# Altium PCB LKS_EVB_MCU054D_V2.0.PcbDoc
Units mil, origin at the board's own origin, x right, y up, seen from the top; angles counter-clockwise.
Board outline 2625 x 1560 mil, 2 copper layers (Top Layer, Bottom Layer); 33 components, 57 nets, 169 pads, 53 vias.
Unrouted connection lines stored in the file: 24.
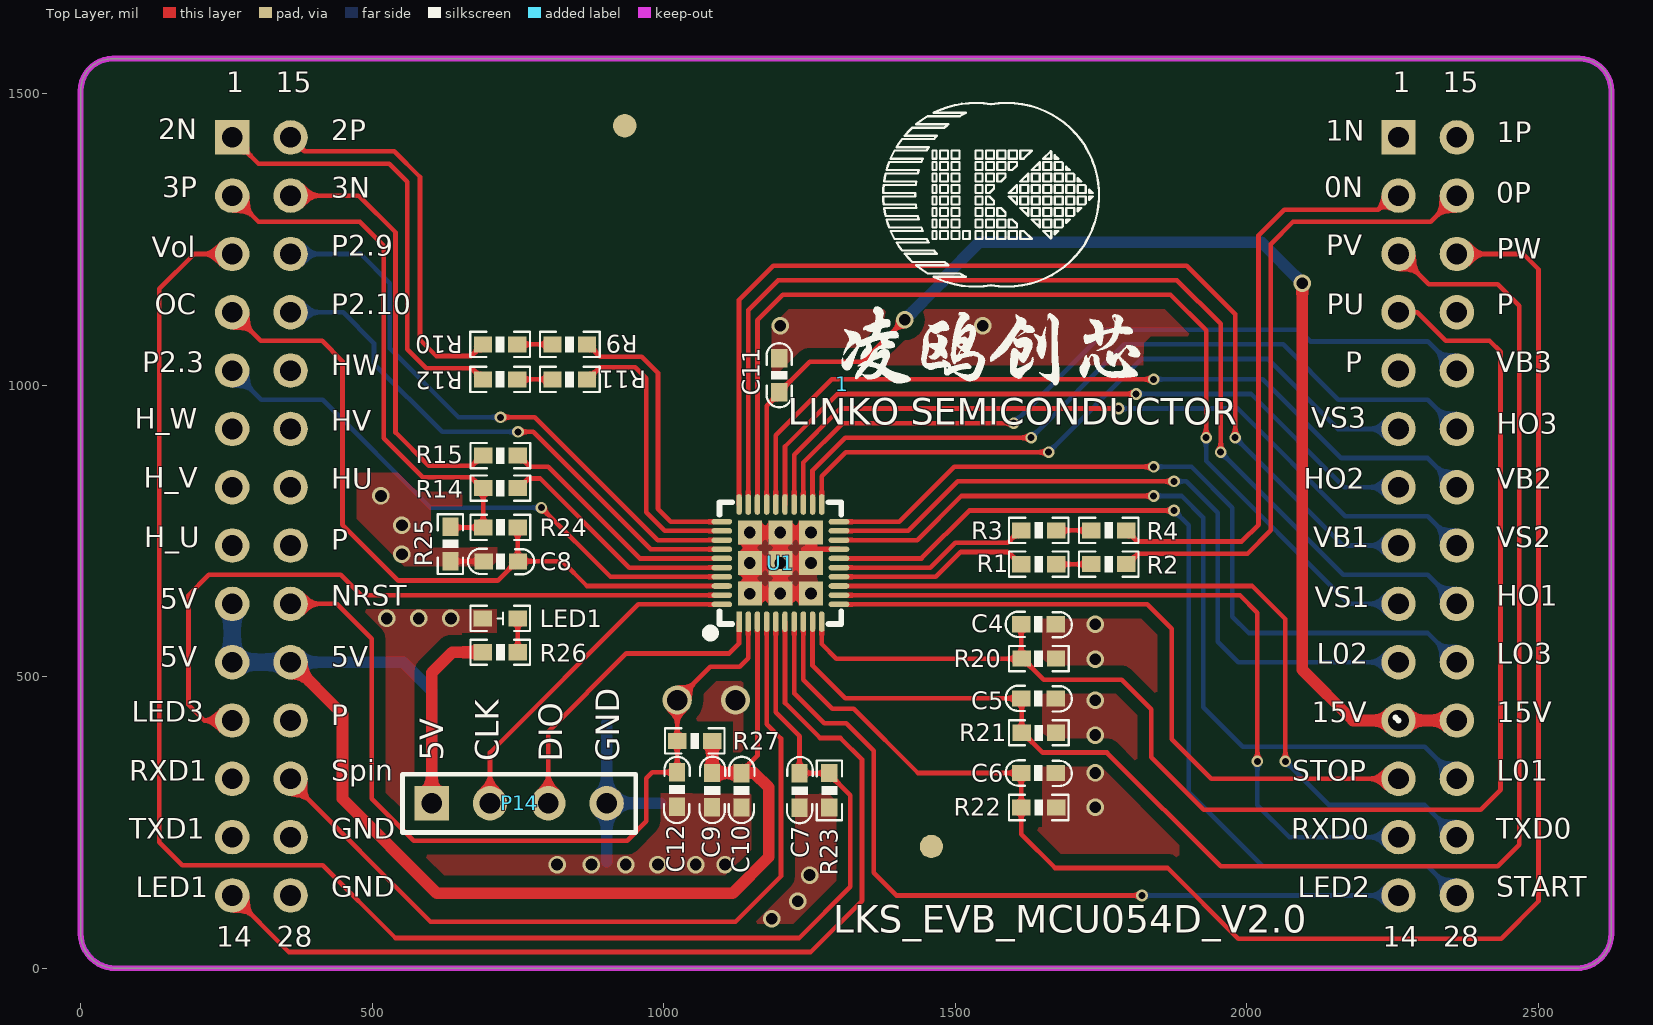
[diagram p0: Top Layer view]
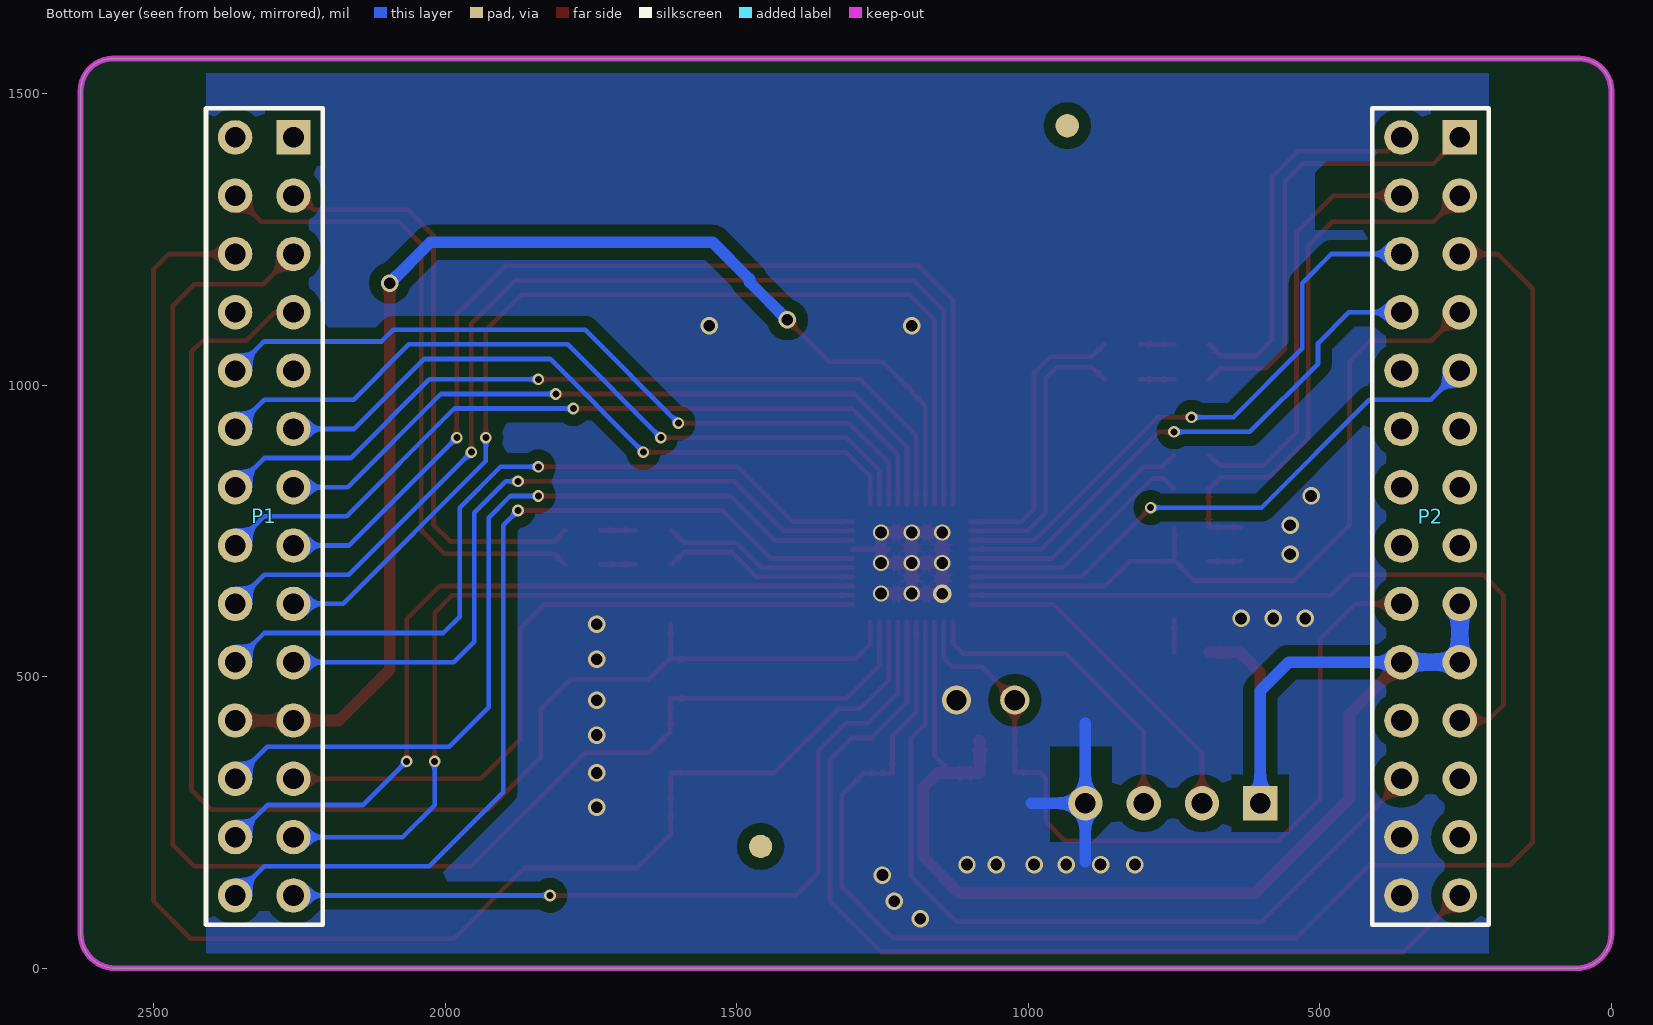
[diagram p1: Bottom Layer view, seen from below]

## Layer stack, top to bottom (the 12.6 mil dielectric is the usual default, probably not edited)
Top Solder: solder mask 0.4, Solder Resist, Dk 3.5
Top Layer: signal copper 1.4
Dielectric1: dielectric 12.6, FR-4, Dk 4.8
Bottom Layer: signal copper 1.4
Bottom Solder: solder mask 0.4, Solder Resist, Dk 3.5

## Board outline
0,60 ccw(c60,60) 60,0 2565,0 ccw(c2565,60) 2625,60 2625,1505 ccw(c2570,1505) 2570,1560 55,1560 ccw(c55,1505) 0,1505

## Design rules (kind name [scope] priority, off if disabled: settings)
Clearance Clearance_1 [InPolygon] p1: gap=20 ignorepadtopadclearanceinfootprint=FALSE except(0: Arc-Hole Track-Hole SMDPad-Hole THPad-Hole Via-Hole Fill-Hole Poly-Hole Region-Hole Text-Hole)
Clearance [All] p2 off: gap=10 ignorepadtopadclearanceinfootprint=FALSE except(0: Arc-Hole Track-Hole SMDPad-Hole THPad-Hole Via-Hole Fill-Hole Poly-Hole Region-Hole Text-Hole)
ComponentClearance [All] p1: gap=0 collisioncheckmode=3 verticalgap=0 showdistances=FALSE
FabricationTestpoint [(IsPad And (OnTopLayer Or OnBottomLayer))] p1: side=3 testpointundercomponent=TRUE minsize=40 maxsize=100 preferedsize=60 minholesize=0 maxholesize=40 preferedholesize=32 testpointgrid=1 allowsidetop=TRUE allowsidebottom=TRUE usegrid=TRUE gridtolerance=0.01
HoleSize [All] p1: absolutevalues=TRUE maxlimit=100 minlimit=0 maxpercent=80.000 minpercent=20.000
PolygonConnect [All] p1: connectstyle=Direct reliefconductorwidth=30 reliefentries=4 polygonreliefangle="90 Angle" airgapwidth=10
RoutingVias [All] p1: holewidth=28 width=50 viastyle="Through Hole" minholewidth=0 minwidth=10 maxholewidth=28 maxwidth=100
SilkToSolderMaskClearance SilkscreenOverComponentPads [IsPad] p1: minsilkscreentomaskgap=10 clearancetoexposedcopper=TRUE
SolderMaskExpansion [All] p1: expansion=4 istentingtop=FALSE
Width [All] p1: maxlimit=100 minlimit=2 preferedwidth=10
26 further rules are at their usual default settings.

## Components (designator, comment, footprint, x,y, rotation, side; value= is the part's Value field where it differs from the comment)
1 "LKS_sign" LKS_LOGO2 1306,1002 r0 top
C4 "1nF/16V" 0603C#1 1612.94,590 r0 top
C5 "1nF/16V" 0603C#1 1612.94,463 r0 top
C6 "1nF/16V" 0603C#1 1612.94,335 r0 top
C7 "100nF/50V" 0603C#1 1232.82,275.63 r90 top
C8 "1nF/50V" 0603C#1 691,698 r0 top
C9 "10uF/10V" 0603C#1 1083,275.94 r90 top
C10 "100nF/50V" 0603C#1 1133,275.76 r90 top
C11 "4.7uF/25V" 0603C#2 1198,1017 r270 top
C12 "100nF/50V" 0603C#1 1023,336 r270 top
LED1 "LED" "LED 0603R" 719.69,600 r180 top
P1 "Header 14X2A" HDR2X14_CEN 2260,1425 r270 bottom
P2 "Header 14X2A" HDR2X14_CEN 260,1425 r270 bottom
P14 "Header 4" HDR1X4 602,283 r0 top
R1 "20K" 0603R#1 1643,692.98 r180 top value=K
R2 "20K" 0603R#1 1763,693 r180 top value=K
R3 "20K" 0603R#1 1643,751 r180 top value=K
R4 "20K" 0603R#1 1763,751 r180 top value=K
R9 "20K" 0603R#2 809.29,1070.01 r0 top value=K
R10 "20K" 0603R#2 689.95,1070.01 r0 top value=K
R11 "20K" 0603R#2 809.29,1010.01 r0 top value=K
R12 "20K" 0603R#2 689.95,1010.01 r0 top value=K
R14 "1K" 0603R#2 690.35,823.35 r0 top value=K
R15 "1K" 0603R#2 690.35,879.35 r0 top value=K
R20 "1K" 0603R#2 1613.65,531 r0 top value=K
R21 "1K" 0603R#2 1613.65,404 r0 top value=K
R22 "1K" 0603R#1 1643,275.81 r0 top value=K
R23 "1K" 0603R#2 1283.82,275.81 r90 top value=K
R24 "1K" 0603R#2 749.4,756 r180 top value=K
R25 "10R" 0603R#2 634,757 r270 top value=K
R26 "3.3K" 0603R#1 719.69,542 r180 top value=330
R27 "20K" 0603R#1 1053,390 r180 top value=330
U1 "LKS32MC054DF6Q8" QFN40 1200,695 r90 top

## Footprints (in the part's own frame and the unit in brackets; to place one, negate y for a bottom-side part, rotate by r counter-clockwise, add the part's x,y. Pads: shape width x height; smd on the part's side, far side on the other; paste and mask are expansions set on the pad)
0603C#1 [mm]
  rect 0.8x0.7 smd: 1(0,0) 2(1.5,0)
  silkscreen extent -0.68,-0.57 2.21,0.55
0603C#2 [mm] "电容"
  rect 0.8x0.7 smd: 1(-0.737,0) 2(0.738,0)
  silkscreen extent -1.4,-0.55 1.4,0.55, body extent -0.8,-0.41 0.8,0.41, height 0.81
0603R#1 [mm] "电阻"
  rect 0.8x0.7 smd: 1(-0.762,0) 2(0.762,0)
  silkscreen extent -1.3,-0.55 1.3,0.55, body extent -0.8,-0.4 0.8,0.4, height 0.45
0603R#2 [mm]
  rect 0.8x0.7 smd: 1(0,0) 2(1.5,0)
  silkscreen extent -0.55,-0.55 2.05,0.55
HDR1X4 [mm] "Connector; Header; 4 Position"
  rect 1.5x1.5 hole 0.9: 1(0,0)
  round 1.5 hole 0.9: 2(2.54,0) 3(5.08,0) 4(7.62,0)
  silkscreen extent -1.27,-1.27 8.89,1.27
HDR2X14_CEN [mm] "Connector; Header; 14x2 Position"
  rect 1.5x1.5 hole 0.9: 1(0,0)
  round 1.5 hole 0.9: 2(2.54,0) 3(5.08,0) 4(7.62,0) 5(10.16,0) 6(12.7,0) 7(15.24,0) 8(17.78,0) 9(20.32,0) 10(22.86,0) 11(25.4,0) 12(27.94,0) 13(30.48,0) 14(33.02,0) 15(0,-2.54) 16(2.54,-2.54) 17(5.08,-2.54) 18(7.62,-2.54) 19(10.16,-2.54) 20(12.7,-2.54) 21(15.24,-2.54) 22(17.78,-2.54) 23(20.32,-2.54) 24(22.86,-2.54) 25(25.4,-2.54) 26(27.94,-2.54) 27(30.48,-2.54) 28(33.02,-2.54)
  silkscreen extent -1.27,-3.81 34.29,1.27
"LED 0603R" [mm] "LED"
  rect 0.8x0.7 smd: 1(-0.762,0) 2(0.762,0)
  silkscreen extent -1.3,-0.55 1.3,0.55, body extent -0.8,-0.4 0.8,0.4, height 0.47
LKS_LOGO2 [mil] "标?"
  silkscreen extent 70,167 440,482
QFN40 [mm] "LINKO-084D"
  rect 1.05x1.05 smd: 0(-1.33,-1.33) 0(-1.33,0) 0(-1.33,1.33) 0(0,1.33) 0(0,0) 0(0,-1.33) 0(1.33,-1.33) 0(1.33,0) 0(1.33,1.33)
  rect 0.9x0.24 smd: 1(-2.55,1.8)
  oval 0.9x0.24 smd: 2(-2.55,1.4) 3(-2.55,1) 4(-2.55,0.6) 5(-2.55,0.2) 6(-2.55,-0.2) 7(-2.55,-0.6) 8(-2.55,-1) 9(-2.55,-1.4) 10(-2.55,-1.8) 21(2.55,-1.8) 22(2.55,-1.4) 23(2.55,-1) 24(2.55,-0.6) 25(2.55,-0.2) 26(2.55,0.2) 27(2.55,0.6) 28(2.55,1) 29(2.55,1.4) 30(2.55,1.8)
  oval 0.24x0.9 smd: 11(-1.8,-2.55) 12(-1.4,-2.55) 13(-1,-2.55) 14(-0.6,-2.55) 15(-0.2,-2.55) 16(0.2,-2.55) 17(0.6,-2.55) 18(1,-2.55) 19(1.4,-2.55) 20(1.8,-2.55) 31(1.8,2.55) 32(1.4,2.55) 33(1,2.55) 34(0.6,2.55) 35(0.2,2.55) 36(-0.2,2.55) 37(-0.6,2.55) 38(-1,2.55) 39(-1.4,2.55) 40(-1.8,2.55)
  silkscreen extent -3.16,-2.65 2.65,3.16, body extent -3,-3 3,3, height 0.9

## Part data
C4 C5 C6: library part CAP, "Capacitor"
C7 C8 C9 C10 C11 C12: library part C, "Capacitor"
LED1: "LED_Light"
P1 P2: "Header, 14-Pin, Dual row"
P14: "Header, 4-Pin"
R1 R2 R3 R4 R9 R10 R11 R12 R14 R15 R20 R21 R22 R23 R24 R25 R26 R27: library part Res, "Resistor"
U1: "芯片"

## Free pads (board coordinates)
  round 50 hole 35: 0(1123,460) 1(1023,460)
  round 40 all layers, no hole: 1(933,1445) 2(1459,209)

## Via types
v1: diameter 30, hole 20, Top Layer to Bottom Layer, 25 vias
v2: diameter 20, hole 12, Top Layer to Bottom Layer, 19 vias
v3: diameter 28, hole 20, Top Layer to Bottom Layer, 8 vias
v4: diameter 31.5, hole 19.68, Top Layer to Bottom Layer, 1 vias

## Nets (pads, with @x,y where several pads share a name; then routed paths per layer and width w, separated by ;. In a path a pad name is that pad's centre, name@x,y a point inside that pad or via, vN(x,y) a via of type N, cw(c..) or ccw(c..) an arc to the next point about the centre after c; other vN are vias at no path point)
+5V: C9.2 C10.2 P2.9 P2.10 P2.24 P14.1 R26.2 R27.1 U1.3 | length 2630.5
  Top Layer w8: C10.2@1132.91,334.91 1132.91,336.7 1160.63,364.42 U1.3
  Top Layer w20: P2.24 449,436 449,291 611,129 1118,129 1180,191 1180,310.26 1155.44,334.82 C10.2 ; P14.1 602,507 637,542 R26.2 ; C9.2 R27.1 R27.1@1084.97,390 ; C9.2@1083.09,334.91 C10.2@1132.91,334.91
  Bottom Layer w20: P2.24 553,525 602,476 P14.1
  Bottom Layer w30: P2.9 P2.10 P2.24
+15V: C11.2 P1.11 P1.25 U1.27 | length 2202.1
  Top Layer w8: U1.27 1176.38,964.35 1198,985.98 C11.2 1198,989.91 1207.78,999.69 1209.75,999.69 1250.05,1040 1341,1040 v1(1413,1112)
  Top Layer w20: v1(2095,1175) 2095,512 2182,425 P1.11 P1.25
  Bottom Layer w20: v1(1413,1112) 1477.96,1176.96 1477.96,1181.96 1541,1245 2025,1245 v1(2095,1175)
GND: C4.2 C5.2 C6.2 C7.1 C8.1 C9.1 C10.1 C11.1 C12.2 LED1.2 P2.16 P2.27 P2.28 P14.4 pad.0 R15.1 R20.2 R21.2 R22.2 R23.1 R25.2 U1.0 U1.17 | length 1741.6
  Top Layer w8: P2.16 477,1325 540,1262 540,919 597,862 671.03,862 688.38,879.35 R15.1 ; R25.2 690.94,697.94 C8.1
  Top Layer w10: 1240.38,718.62 1252.36,718.62 ; 1264,718.62 U1.17
  Top Layer w20: v3(1147.64,695) v3(1200,695) ; v3(1252.36,642.64) v3(1200,642.64) ; v3(1200,642.64) v3(1200,695) ; v3(1200,642.64) v4(1147.64,642.64) v3(1147.64,747.36) v3(1200,747.36) ; v3(1200,695) v3(1200,747.36) ; v3(1200,695) v3(1252.36,695) 1252.36,706.98 1252.36,718.62 v3(1252.36,747.36) v3(1200,747.36)
  Bottom Layer w20: 902,183 P14.4 ; 902,420 P14.4 ; 995,283 P14.4
  other v1: 1185,85 1230,115 1250,160 817,178 876,178 935,178 990,178 1055,178 1105,178 1740,276 1740,335 1740,400 1740,460 1740,530 1740,590 525,600 580,600 635,600 551,710 551,760 515,810 1200,1102 1547,1102
HALL_U: P2.8
HALL_V: P2.7
HALL_W: P2.6
HO1: P1.23 U1.29 | length 1928.5
  Top Layer w8: U1.29 1144.88,1128.88 1196,1180 1880,1180 1955,1105 v2(1955,885)
  Bottom Layer w8: v2(1955,885) 2165,675 2310,675 P1.23
HO2: P1.7 U1.25 | length 1255.2
  Top Layer w8: U1.25 1207.87,894.87 1298,985 v2(1810,985)
  Bottom Layer w8: v2(1810,985) 2007,985 2167,825 P1.7
HO3: P1.20 U1.22 | length 1313.1
  Top Layer w8: U1.22 1255.12,854.12 1311,910 v2(1630,910)
  Bottom Layer w8: v2(1630,910) 1790,1070 2062,1070 2157,975 2310,975 P1.20
HU: P2.21
HV: P2.20
HW: P2.19
LED1: P2.14 U1.6 | length 1710.5
  Top Layer w8: P2.14 357,28 1252,28 1340,116 1340,358 1303,395 1268,395 1207.87,455.13 U1.6
LED2: P1.14 U1.7 | length 1425.5
  Top Layer w8: U1.7 1223.62,471.38 1275,420 1313,420 1360,373 1360,164 1399,125 v2(1820,125)
  Bottom Layer w8: v2(1820,125) P1.14
LED3: P2.11 U1.39 | length 1217.8
  Top Layer w8: P2.11 212,425 185,452 185,640 220,675 446,675 481.12,639.88 U1.39
LO1: P1.26 U1.18 | length 1482.2
  Top Layer w8: U1.18 1434.37,734.37 1510,810 v2(1840,810)
  Bottom Layer w8: v2(1840,810) 1888,810 1925,773 1925,448 1993,380 2305,380 P1.26
LO2: P1.10 U1.19 | length 1252.6
  Top Layer w8: U1.19 1419.12,750.12 1504,835 v2(1875,835)
  Bottom Layer w8: v2(1875,835) 1896,835 1950,781 1950,560 1985,525 P1.10
LO3: P1.24 U1.20 | length 1346.9
  Top Layer w8: U1.20 1403.87,765.87 1498,860 v2(1840,860)
  Bottom Layer w8: v2(1840,860) 1905,860 1975,790 1975,603 2003,575 2310,575 P1.24
NetLED1_1: LED1.1 R26.1 | length 58
  Top Layer w8: R26.1 LED1.1
NetR1_1: R1.1 R2.2 | length 60
  Top Layer w8: R1.1 R2.2
NetR3_1: R3.1 R4.2 | length 60
  Top Layer w8: R3.1 R4.2
NetR9_1: R9.1 R10.2 | length 59.9
  Top Layer w8: R10.2 R9.1@808.95,1070.01
NetR11_1: R11.1 R12.2 | length 59.9
  Top Layer w8: R12.2 R11.1@808.95,1010.01
NRST: C12.1 P2.23 pad.1@1023,460 R27.2 U1.2 | length 1421.9
  Top Layer w8: P2.23 439,625 499,565 499,291 571,219 937,219 970,252 970,326 980,336 C12.1 R27.2 1023,460 1080,517 1130,517 1144.88,531.88 U1.2
OC: C8.2 P2.4 R24.1 U1.38 | length 1283.7
  Top Layer w8: P2.4 309,1076 414,1076 449,1041 449,761 545,665 715.09,665 748.09,698 C8.2 ; R24.1 749.4,698.65 C8.2 ; U1.38 868.37,655.63 826,698 C8.2
OPA0_IN: R11.2 U1.32 | length 492
  Top Layer w8: R11.2@869,1009.35 R11.2 869.97,1010.01 890.97,1031.01 950.99,1031.01 970,1012 970,782 1001.88,750.12 U1.32
OPA0_IP: R9.2 U1.31 | length 492.1
  Top Layer w8: R9.2@869.97,1070.01 890.97,1049.01 961.99,1049.01 990,1021 990,788 1012.13,765.87 U1.31
OPA1_IN: R15.2 U1.35 | length 423.3
  Top Layer w8: R15.2 751.37,879.35 770.72,860 802,860 880.56,781.44 959.13,702.87 U1.35
OPA1_IP: R14.2 U1.36 | length 420.4
  Top Layer w8: R14.2 751.37,823.35 768.02,840 788,840 940.87,687.13 U1.36
OPA2_IN: R3.2 U1.15 | length 339.1
  Top Layer w8: U1.15 1457.13,687.13 1500,730 1590.03,730 1611.03,751 R3.2
OPA2_IP: R1.2 U1.14 | length 339
  Top Layer w8: U1.14 1466.38,671.38 1509,714 1590.01,714 1611.03,692.98 R1.2
P2.3: P2.5 U1.37 | length 986.1
  Top Layer w8: v2(790,790) 908.62,671.38 U1.37
  Bottom Layer w8: P2.5 310,975 415,975 600,790 v2(790,790)
P2.9: P2.17 U1.33 | length 1008.4
  Top Layer w8: v2(720,945) 779,945 989.63,734.37 U1.33
  Bottom Layer w8: P2.17 480,1225 530,1175 530,1063 648,945 v2(720,945)
P2.10: P2.18 U1.34 | length 928.4
  Top Layer w8: v2(750,920) 776,920 977.38,718.62 U1.34
  Bottom Layer w8: P2.18 450,1125 503,1072 503,1037 620,920 v2(750,920)
PGND: P1.1 P1.2 P2.1 P2.2 R4.1 R12.1 R14.1 R24.2 R25.1 | length 2740.5
  Top Layer w8: P2.2 305,1280 479,1280 520,1239 520,909 587,842 669.73,842 688.38,823.35 R14.1 692.32,823.35 690.35,821.38 R24.2 635,756 R25.1 ; P2.1 305,1380 529,1380 560,1349 560,1062 592.99,1029.01 670.95,1029.01 R12.1 ; R4.1 1794.97,751 1804.75,741.22 1804.75,739.25 1812,732 1991,732 2020,761 2020,1257 2064,1301 2225,1301 2249,1325 P1.2
PU: C4.1 P1.4 R20.1 U1.10 | length 2395.9
  Top Layer w8: U1.10 1270.87,556.13 1296,531 R20.1 ; C4.1 1612.94,531.71 R20.1 ; P1.4 2292,1125 2341,1076 2416,1076 2435,1057 2435,306 2401,272 1926,272 1836,362 1836,444 1785,495 1651.62,495 1615.62,531 R20.1
PV: C5.1 P1.3 R21.1 U1.9 | length 2647.4
  Top Layer w8: U1.9 1255.12,518.88 1311,463 C5.1 1613.65,462.29 R21.1 1615.62,404 1649.62,370 1760,370 1955,175 2430,175 2467,212 2467,1136 2430,1173 2312,1173 P1.3
PW: C6.1 P1.17 R22.1 U1.8 | length 2867.1
  Top Layer w8: U1.8 1239.37,494.63 1289,445 1326,445 1436,335 C6.1 1613,334.95 R22.1 1613,230 1671,172 1864,172 1985,51 2436,51 2500,115 2500,1199 2474,1225 P1.17
RXD0: P1.13 U1.12 | length 1324.8
  Top Layer w8: U1.12 1988.12,639.88 2018,610 v2(2018,355)
  Bottom Layer w8: v2(2018,355) 2018,280 2073,225 P1.13
RXD1: P2.12
SPIN: P2.26 U1.4 | length 1419.5
  Top Layer w8: P2.26@360,320 600,80 1123,80 1201,158 1201,394 1176.38,418.62 U1.4
START1: P1.28 U1.16 | length 1635.3
  Top Layer w8: U1.16 1441.87,702.87 1524,785 v2(1875,785)
  Bottom Layer w8: v2(1875,785) 1900,760 1900,302 2027,175 2310,175 P1.28
STOP1: P1.12 U1.11 | length 1194.2
  Top Layer w8: U1.11 1828.87,624.13 1871,582 1871,393 1939,325 P1.12
SWCLK: P14.2 U1.40 | length 589.9
  Top Layer w8: P14.2 702,370 956.13,624.13 U1.40
SWDIO: P14.3 U1.1 | length 550.2
  Top Layer w8: P14.3 802,406 936,540 1112,540 1129.13,557.13 U1.1
TXD0: P1.27 U1.13 | length 1380.9
  Top Layer w8: U1.13 2009.37,655.63 2066,599 v2(2066,355)
  Bottom Layer w8: v2(2066,355) 2141,280 2305,280 P1.27
TXD1: P2.13
UP-: P2.15 R10.1 | length 657
  Top Layer w8: P2.15 384,1401 538,1401 582,1357 582,1078 609.99,1050.01 669.95,1050.01 R10.1
VB1: P1.8 U1.30 | length 1829
  Top Layer w8: U1.30 1129.13,1146.13 1188,1205 1897,1205 1980,1122 v2(1980,910)
  Bottom Layer w8: v2(1980,910) 2165,725 P1.8
VB2: P1.21 U1.26 | length 1402.9
  Top Layer w8: U1.26 1192.13,914.13 1288,1010 v2(1840,1010)
  Bottom Layer w8: v2(1840,1010) 2027,1010 2162,875 2310,875 P1.21
VB3: P1.19 U1.23 | length 1315.9
  Top Layer w8: U1.23 1239.37,867.37 1307,935 v2(1600,935)
  Bottom Layer w8: v2(1600,935) 1760,1095 2089,1095 2109,1075 2310,1075 P1.19
VOL_ADC: C7.2 P2.3 R23.2 U1.5 | length 2925.6
  Top Layer w8: P2.3 195,1225 135,1165 135,216 174,177 415,177 540,52 1232,52 1320,140 1320,296.72 1283.64,333.08 1283.64,334.69 C7.2 1232.82,398.18 1192.13,438.87 U1.5
VP-: P1.15
VS1: P1.9 U1.28 | length 1784.3
  Top Layer w8: U1.28 1160.63,1111.63 1204,1155 1869,1155 1930,1094 v2(1930,910)
  Bottom Layer w8: v2(1930,910) 1930,870 2175,625 P1.9
VS2: P1.22 U1.24 | length 1351.8
  Top Layer w8: U1.24 1223.62,880.62 1303,960 v2(1780,960)
  Bottom Layer w8: v2(1780,960) 1984,960 2169,775 2310,775 P1.22
VS3: P1.6 U1.21 | length 1170.6
  Top Layer w8: U1.21 1270.87,843.87 1312,885 v2(1660,885)
  Bottom Layer w8: v2(1660,885) 1820,1045 2036,1045 2156,925 P1.6
WP-: P1.16 R2.1 | length 1116.4
  Top Layer w8: R2.1 1794.97,693 1812.97,711 2001,711 2041,751 2041,1242 2079,1280 2315,1280 P1.16
pads on no net: P1.5 P1.18 P2.22 P2.25

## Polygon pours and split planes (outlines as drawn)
GND on Bottom Layer "Top Layer-No Net 1" (solid, remove dead copper, pour order 15): 210,1560 210,0 2410,0 2410,1560
GND on Top Layer "GND_L01_P016" (solid, remove dead copper, pour order 16): 210,1560 210,0 2410,0 2410,1560

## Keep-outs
Keep-Out Layer:
  the board outline again, w10

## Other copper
Top Layer:
  pour cut-out: 288,1363 284.53,1359.53 284.53,1223 409.95,1223 409.95,850 833.08,850 828,1361
  pour cut-out: 260,325 449,325 450,324 450,27 260,27 259,28
  pour cut-out: 1884,240 1884,158 1910,158 1910,215
  pour cut-out: 1822.61,1034.47 1824.14,1036 1937,1036 1937,1077 1938,1078 1932,1084 1835,1084 1823,1072
  pour cut-out: 855,382 855,253 892,216 893,217 963,217 963,381 962,382 961,381 856,381
Bottom Layer:
  pour cut-out: 303,1384 489,1384 509,1364 509,1266 313,1266 304,1275
  pour cut-out: 856,381 856,254 855,253 891.5,216.5 962.5,216.5 963,217 963,381

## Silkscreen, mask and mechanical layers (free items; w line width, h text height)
Top Overlay:
  drawing of 8 lines, arcs and shapes, not listed
  text "2N" at 133.18,1410 h60
  text "2P" at 430,1408 h60
  text "1N" at 2135.33,1407 h60
  text "1P" at 2428.06,1405 h60
  text "3P" at 140.28,1310 h60
  text "0N" at 2132.61,1310 h60
  text "3N" at 429.94,1309 h60
  text "0P" at 2428,1301 h60
  text "PV" at 2136.11,1211 h60
  text "P2.9" at 430,1210 h60
  text "Vol" at 122.3,1207 h60
  text "PW" at 2428.06,1205 h60
  text "OC" at 126.91,1110 h60
  text "P2.10" at 430,1110 h60
  text "PU" at 2136.55,1110 h60
  text "P" at 2428.06,1110 h60
  text "P2.3" at 105.54,1010 h60
  text "P" at 2168.3,1010 h60
  text "VB3" at 2428,1010 h60
  text "HW" at 430,1005 h60
  text "VS3" at 2110.02,915 h60
  text "H_W" at 92.94,913 h60
  text "HV" at 430,910 h60
  text "HO3" at 2428.06,905 h60
  text "H_V" at 108.26,812 h60
  text "HU" at 430,810 h60
  text "HO2" at 2097.81,810 h60
  text "VB2" at 2428,810 h60
  text "H_U" at 108.7,710 h60
  text "VB1" at 2114.02,710 h60
  text "VS2" at 2428,710 h60
  text "P" at 430,706 h60
  text "NRST" at 430,610 h60
  text "HO1" at 2428.06,610 h60
  text "VS1" at 2116.29,607 h60
  text "5V" at 136.51,605 h60
  text "L02" at 2120.01,510 h60
  text "LO3" at 2428.06,510 h60
  text "5V" at 136.51,505 h60
  text "5V" at 429.94,505 h60
  text "LED3" at 88,411 h60
  text "15V" at 2110.85,410 h60
  text "15V" at 2428.06,410 h60
  text "P" at 430,405 h60
  text "5V" at 622,356 h40 r90
  text "CLK" at 717,355 h40 r90
  text "DIO" at 826,354 h40 r90
  text "GND" at 924,354 h40 r90
  text "RXD1" at 83.62,310 h60
  text "Spin" at 429.94,310 h60
  text "STOP" at 2077.44,310 h60
  text "L01" at 2428.06,310 h60
  text "TXD1" at 83.73,210 h60
  text "GND" at 430,210 h60
  text "RXD0" at 2076,210 h60
  text "TXD0" at 2428,210 h60
  text "GND" at 430,111 h60
  text "START" at 2428,111 h60
  text "LED1" at 94.27,110 h60
  text "LED2" at 2087.1,110 h60
  text "LKS_EVB_MCU054D_V2.0" at 1291,46 h80
Top Solder:
  circle w78: c1459,209 r17
  circle w78: c933,1445 r17
Mechanical 1:
  the board outline again, w10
